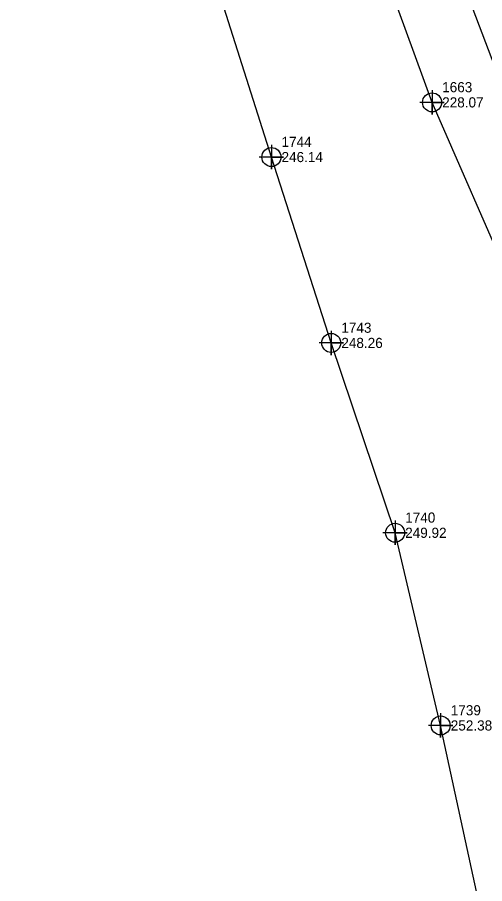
# Model space of a CAD drawing. Extents: x 2130962 to 2131465, y 643052 to 644206.
# Drawn here: x 2130964.8 to 2131080.2, y 643795.8 to 644009.5 of the extents above; entities that cross this region are included whole.
import ezdxf

# ---------------------------------------------------------------- set-up
doc = ezdxf.new("R2010")
doc.units = 0
for name, color, linetype in [('Exist DTM Breakline', 7, 'Continuous'), ('Exist DTM Breakline Cogo Elevation', 7, 'Continuous'), ('Exist DTM Breakline Cogo Number', 7, 'Continuous'), ('Exist DTM Breakline Cogo Point CELL', 7, 'Continuous'), ('Exist DTM Drainline', 7, 'Continuous'), ('Exist DTM Drainline Cogo Elevation', 7, 'Continuous'), ('Exist DTM Drainline Cogo Number', 7, 'Continuous'), ('Exist DTM Drainline Cogo Point CELL', 7, 'Continuous'), ('Exist Roads EOT', 7, 'Continuous'), ('Exist Roads Soil', 7, 'Continuous')]:
    doc.layers.add(name, color=color, linetype=linetype)

msp = doc.modelspace()

# ---------------------------------------------------------------- linework, layer by layer
at = {"layer": 'Exist DTM Breakline'}
msp.add_lwpolyline([(2131139.0887, 643604.6918), (2131124.996, 643650.6897), (2131108.0385, 643698.079), (2131093.5223, 643741.563), (2131079.9108, 643785.8518), (2131069.3516, 643834.7964), (2131058.0914, 643882.3322), (2131042.317, 643929.1682), (2131027.5453, 643975.0277), (2131014.156, 644017.233), (2130995.2084, 644066.2506), (2130976.662, 644110.4992), (2130964.7831, 644158.2254)], dxfattribs=at)
at = {"layer": 'Exist DTM Breakline Cogo Point CELL'}
for points in [[(2131027.5453, 643978.0277), (2131027.5453, 643972.0277), (2131027.5453, 643975.0277), (2131030.5453, 643975.0277), (2131024.5453, 643975.0277)], [(2131042.317, 643932.1682), (2131042.317, 643926.1682), (2131042.317, 643929.1682), (2131045.317, 643929.1682), (2131039.317, 643929.1682)], [(2131058.0914, 643885.3322), (2131058.0914, 643879.3322), (2131058.0914, 643882.3322), (2131061.0914, 643882.3322), (2131055.0914, 643882.3322)], [(2131069.3516, 643837.7964), (2131069.3516, 643831.7964), (2131069.3516, 643834.7964), (2131072.3516, 643834.7964), (2131066.3516, 643834.7964)]]:
    msp.add_lwpolyline(points, dxfattribs=at)
for centre in [(2131027.5453, 643975.0277), (2131042.317, 643929.1682), (2131058.0914, 643882.3322), (2131069.3516, 643834.7964)]:
    msp.add_circle(centre, 2.344, dxfattribs=at)
at = {"layer": 'Exist DTM Drainline'}
msp.add_lwpolyline([(2131093.1541, 643926.3006), (2131087.2748, 643942.7791), (2131067.2265, 643988.5191), (2131050.4927, 644034.5509), (2131030.3027, 644079.1881), (2131009.8205, 644123.8359), (2130986.2155, 644168.1871)], dxfattribs=at)
at = {"layer": 'Exist DTM Drainline Cogo Point CELL'}
msp.add_lwpolyline([(2131067.2265, 643991.5191), (2131067.2265, 643985.5191), (2131067.2265, 643988.5191), (2131070.2265, 643988.5191), (2131064.2265, 643988.5191)], dxfattribs=at)
msp.add_circle((2131067.2265, 643988.5191), 2.344, dxfattribs=at)
at = {"layer": 'Exist Roads EOT'}
msp.add_spline([(2131166.718, 643215.2083), (2131172.3866, 643217.1804), (2131211.4056, 643247.1499), (2131223.758, 643268.7314), (2131228.3848, 643317.935), (2131225.533, 643367.8628), (2131222.2486, 643417.1873), (2131217.9619, 643466.6275), (2131212.8794, 643516.2377), (2131206.5633, 643565.5764), (2131198.9021, 643614.6757), (2131189.6851, 643663.4055), (2131179.3985, 643712.1311), (2131168.3085, 643760.7185), (2131155.755, 643808.9129), (2131141.6748, 643856.5528), (2131126.5354, 643904.2758), (2131110.3559, 643951.0191), (2131092.4533, 643998.1348), (2131073.722, 644043.631), (2131053.1654, 644089.359), (2131032.0052, 644134.0908), (2131009.0644, 644179.3802)], degree=3, dxfattribs=at)
at = {"layer": 'Exist Roads Soil'}
msp.add_lwpolyline([(2131224.8674, 643317.753), (2131220.141, 643317.6487), (2131216.7544, 643367.544), (2131211.084, 643416.163), (2131207.4344, 643466.363), (2131202.1097, 643514.7948), (2131195.0195, 643564.3052), (2131187.2605, 643612.6498), (2131179.506, 643660.9545), (2131164.8317, 643709.0781), (2131153.9175, 643755.9834), (2131140.8896, 643804.492), (2131127.2512, 643851.9231), (2131113.4771, 643899.8082), (2131083.6685, 643994.997), (2131066.191, 644040.9476), (2131049.1539, 644087.3869)], dxfattribs=at)

# ---------------------------------------------------------------- texts
at = {"layer": 'Exist DTM Breakline Cogo Elevation'}
for s, p in [('246.14', (2131030.0453, 643973.7777)), ('248.26', (2131044.817, 643927.9182)), ('249.92', (2131060.5914, 643881.0822)), ('252.38', (2131071.8516, 643833.5464))]:
    msp.add_text(s, height=2.5, dxfattribs=at).set_placement(p)
at = {"layer": 'Exist DTM Breakline Cogo Number'}
for s, p in [('1744', (2131030.0453, 643977.5277)), ('1743', (2131044.817, 643931.6682)), ('1740', (2131060.5914, 643884.8322)), ('1739', (2131071.8516, 643837.2964))]:
    msp.add_text(s, height=2.5, dxfattribs=at).set_placement(p)
at = {"layer": 'Exist DTM Drainline Cogo Elevation'}
msp.add_text('228.07', height=2.5, dxfattribs=at).set_placement((2131069.7265, 643987.2691))
at = {"layer": 'Exist DTM Drainline Cogo Number'}
msp.add_text('1663', height=2.5, dxfattribs=at).set_placement((2131069.7265, 643991.0191))

doc.saveas('drawing.dxf')
